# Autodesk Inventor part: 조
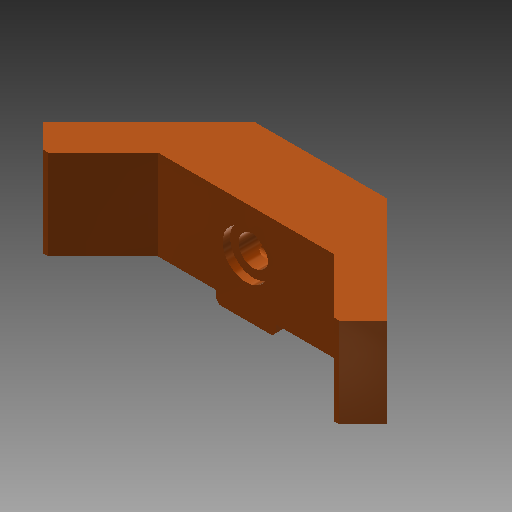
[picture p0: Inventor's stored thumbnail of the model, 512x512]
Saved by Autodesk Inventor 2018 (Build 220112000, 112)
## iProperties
Created: 2019-04
Part Number: 조
Material: 알루미늄 6061
Document SubType Name: Modeling
Designer: mduedu
Density: 1 g/cm^3
Appearance: Smooth - Light Orange
Author: mduedu
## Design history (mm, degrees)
sketch "스케치1"
  geometry: L1 (45.962, 0)-(0, -45.962); L2 (0, -45.962)-(-45.962, 0); L3 (-45.962, 0)-(0, 45.962); L4 (0, 45.962)-(45.962, 0); L5 (45.962, 0)-(-45.962, 0); L6 (0, -45.962)-(0, 45.962); 1 further point
  constraints: 12 end point, 2 midpoint, 2 parallel, 2 perpendicular, 1 horizontal
  dimensions: "d0" = 65 distance of L1.end L2.end
extrude "돌출1" new body sketch "스케치1" distance "d2" = 27; taper "d3" = 0 deg
chamfer "모따기1" distance "d4" = 25; stored, may be unused: second distance "d5" = 2, angle "d6" = 45 deg
sketch "스케치2"
  geometry: L1 (-17.678, 28.284)-(-45.962, 0) reference; L2 (-17.678, 28.284)-(17.678, 28.284) reference; L3 (45.962, 0)-(17.678, 28.284) reference; L4 (-45.962, 0)-(0, -45.962) reference; L5 (0, -45.962)-(45.962, 0) reference; L6 (-23.536, 8.284)-(23.536, 8.284); L7 (-23.536, 8.284)-(-38.891, -7.071); L8 (38.891, -7.071)-(23.536, 8.284); 1 further point
  constraints: 6 end point, 3 parallel, 2 point on line
  dimensions: "d7" = 20 distance between parallel lines of L6 L2; "d8" = 10 distance between parallel lines of L1 L7; "d9" = 10 distance between parallel lines of L3 L8
extrude "돌출2" cut sketch "스케치2" extent not by distance; stored distance "d10" = 27; taper "d11" = 0 deg
sketch "스케치3"
  geometry: L1 (63.64, -27)-(63.64, 0) reference; L2 (56.569, -27)-(63.64, -27) reference; L3 (-28.284, -27)-(-28.284, 0) reference; L4 (-28.284, -27)-(-21.213, -27) reference; L5 (63.64, -27)-(25.678, -27); L6 (25.678, -27)-(25.678, -24); L7 (25.678, -24)-(63.64, -24); L8 (63.64, -24)-(63.64, -27); L9 (-28.284, -27)-(9.678, -27); L10 (9.678, -27)-(9.678, -24); L11 (9.678, -24)-(-28.284, -24); L12 (-28.284, -24)-(-28.284, -27); L13 (41.213, 0)-(-5.858, 0) reference; L14 (17.678, -27)-(17.678, 0)
  constraints: 18 end point, 4 parallel, 2 horizontal, 2 perpendicular, 1 midpoint, 1 symmetric about line
  dimensions: "d12" = 3 distance between parallel lines of L5 L7; "d14" = 16 distance between parallel lines of L10 L6
extrude "돌출3" cut sketch "스케치3" extent not by distance; stored distance "d15" = 27; taper "d16" = 0 deg
sketch "스케치4"
  geometry: L1 (31.536, -27)-(15.536, -27) reference; L2 (31.536, -24)-(47.071, -24) reference; 3 further points
  constraints: 1 midpoint, 1 vertical alignment
  dimensions: "d17" = 12 distance from line of L2 point (23.536, -12)
hole "구멍1" sketch "스케치4" at (23.536, -12) diameter "d18" = 8; stored, may be unused: countersink angle "d22" = 90 deg, drill point angle "d24" = 118 deg; dims "d19" = 6, "d20" = 12.5, "d21" = 2, "d23" = 14
node "작업 평면1"
sketch "스케치5"
  geometry: L1 (0, -15)-(0, 0); L2 (-50, -4)-(50, -4); L3 (50, -4)-(50, -1.75); L4 (-50, -1.75)-(-50, -4); L5 (12, -1.75)-(12, -2.75); L6 (12, -2.75)-(-12, -2.75); L7 (-12, -2.75)-(-12, -1.75); L8 (50, -1.75)-(12, -1.75); L9 (-12, -1.75)-(-50, -1.75); C1 r 4 at (0, 0) reference; 2 further points
  constraints: 18 end point, 4 parallel, 2 midpoint, 2 vertical, 2 vertical alignment, 1 collinear, 1 horizontal, 1 perpendicular, 1 tangent
  dimensions: "d26" = 2.5 diameter of L6 L2; "d28" = 4.5 diameter of L8 L2; "d29" = 24 distance of L5.end L6.end; "d30" = 100 distance between parallel lines of L3 L4
revolve "회전1" sketch "스케치5" stored, may be unused: angle "d31" = 90 deg
chamfer "모따기2" distance "d32" = 1; stored, may be unused: second distance "d33" = 2, angle "d34" = 45 deg
chamfer "모따기3" distance "d35" = 1; stored, may be unused: second distance "d36" = 2, angle "d37" = 45 deg
node "솔리드1"
other parameters: "d25" = -5
